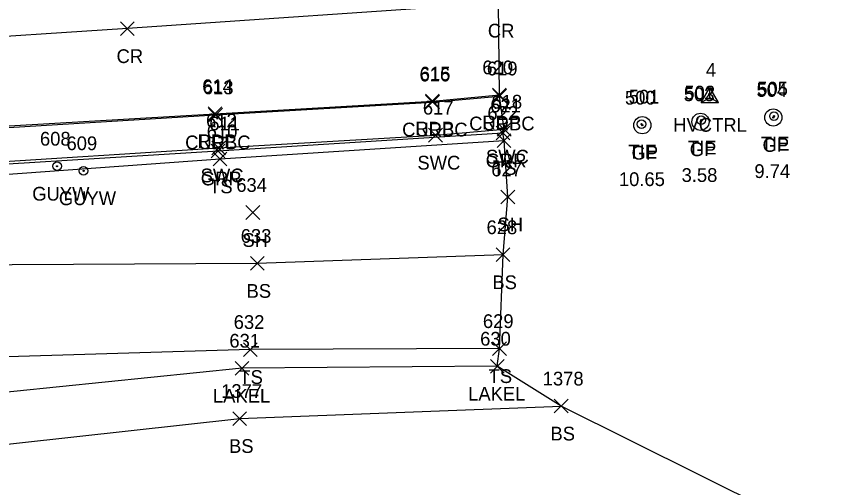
# Model space of a CAD drawing. Extents: x 1715662 to 1717487, y 887396 to 890004.
# Drawn here: x 1717358.8 to 1717478.7, y 888192.4 to 888260.9 of the extents above; entities that cross this region are included whole.
import ezdxf

# ---------------------------------------------------------------- set-up
doc = ezdxf.new("R2010")
doc.units = 0
for name, color, linetype in [('C_A', 7, 'Continuous'), ('C_C', 7, 'Continuous'), ('C_I', 7, 'Continuous'), ('CBP', 7, 'Continuous'), ('CPSM', 7, 'Continuous'), ('L_A', 7, 'Continuous'), ('L_I', 7, 'Continuous'), ('L_TIC', 7, 'Continuous'), ('LAWE', 7, 'Continuous'), ('LELB', 7, 'Continuous'), ('LSOGP', 7, 'Continuous'), ('P_A', 7, 'Continuous'), ('P_I', 7, 'Continuous'), ('P_TIC', 7, 'Continuous'), ('PET', 7, 'Continuous'), ('PRC', 7, 'Continuous'), ('R_A', 7, 'Continuous'), ('R_I', 7, 'Continuous'), ('R_TIC', 7, 'Continuous'), ('RC', 7, 'Continuous'), ('RGP', 7, 'Continuous'), ('RGR', 7, 'Continuous'), ('RSW', 7, 'Continuous'), ('U_A', 7, 'Continuous'), ('U_I', 7, 'Continuous'), ('UPGW', 7, 'Continuous')]:
    doc.layers.add(name, color=color, linetype=linetype)

msp = doc.modelspace()

# ---------------------------------------------------------------- linework, layer by layer
at = {"layer": 'CBP'}
for centre, radius in [((1717468.98, 888246.44), 0.625), ((1717449.72, 888245.27), 0.625), ((1717458.39, 888245.87), 0.625), ((1717458.39, 888245.87), 0.0833), ((1717468.98, 888246.44), 0.0833), ((1717449.72, 888245.27), 0.0833)]:
    msp.add_circle(centre, radius, dxfattribs=at)
at = {"layer": 'CPSM'}
for p, q in [((1717458.39, 888248.45), (1717459.64, 888250.62)), ((1717458.39, 888248.45), (1717459.64, 888250.62)), ((1717458.39, 888248.45), (1717459.64, 888250.62)), ((1717458.39, 888248.45), (1717459.64, 888250.62)), ((1717458.39, 888248.45), (1717459.64, 888250.62)), ((1717458.39, 888248.45), (1717459.64, 888250.62)), ((1717458.39, 888248.45), (1717459.64, 888250.62)), ((1717458.39, 888248.45), (1717459.64, 888250.62)), ((1717458.39, 888248.45), (1717459.64, 888250.62)), ((1717458.39, 888248.45), (1717459.64, 888250.61)), ((1717460.89, 888248.45), (1717459.64, 888250.62)), ((1717459.64, 888249.17), (1717459.64, 888250.62)), ((1717460.89, 888248.45), (1717459.64, 888250.62)), ((1717459.64, 888249.17), (1717459.64, 888250.62)), ((1717460.89, 888248.45), (1717459.64, 888250.62)), ((1717459.64, 888249.17), (1717459.64, 888250.62)), ((1717460.89, 888248.45), (1717459.64, 888250.62)), ((1717459.64, 888249.17), (1717459.64, 888250.62)), ((1717460.89, 888248.45), (1717459.64, 888250.62)), ((1717459.64, 888249.17), (1717459.64, 888250.62)), ((1717460.89, 888248.45), (1717459.64, 888250.62)), ((1717459.64, 888249.17), (1717459.64, 888250.62)), ((1717460.89, 888248.45), (1717459.64, 888250.62)), ((1717459.64, 888249.17), (1717459.64, 888250.62)), ((1717460.89, 888248.45), (1717459.64, 888250.62)), ((1717459.64, 888249.17), (1717459.64, 888250.62)), ((1717460.89, 888248.45), (1717459.64, 888250.62)), ((1717459.64, 888249.17), (1717459.64, 888250.62)), ((1717460.89, 888248.45), (1717459.64, 888250.61)), ((1717459.64, 888249.17), (1717459.64, 888250.61)), ((1717458.39, 888248.45), (1717459.64, 888249.17)), ((1717458.39, 888248.45), (1717459.64, 888249.17)), ((1717458.39, 888248.45), (1717459.64, 888249.17)), ((1717458.39, 888248.45), (1717459.64, 888249.17)), ((1717458.39, 888248.45), (1717459.64, 888249.17)), ((1717458.39, 888248.45), (1717459.64, 888249.17)), ((1717458.39, 888248.45), (1717459.64, 888249.17)), ((1717458.39, 888248.45), (1717459.64, 888249.17)), ((1717458.39, 888248.45), (1717459.64, 888249.17)), ((1717458.39, 888248.45), (1717459.64, 888249.17)), ((1717458.39, 888248.45), (1717460.89, 888248.45)), ((1717458.39, 888248.45), (1717460.89, 888248.45)), ((1717458.39, 888248.45), (1717460.89, 888248.45)), ((1717458.39, 888248.45), (1717460.89, 888248.45)), ((1717458.39, 888248.45), (1717460.89, 888248.45)), ((1717458.39, 888248.45), (1717460.89, 888248.45)), ((1717458.39, 888248.45), (1717460.89, 888248.45)), ((1717458.39, 888248.45), (1717460.89, 888248.45)), ((1717458.39, 888248.45), (1717460.89, 888248.45)), ((1717458.39, 888248.45), (1717460.89, 888248.45)), ((1717459.64, 888249.17), (1717459.64, 888249.17)), ((1717459.64, 888249.17), (1717460.89, 888248.45)), ((1717459.64, 888249.17), (1717459.64, 888249.17)), ((1717459.64, 888249.17), (1717460.89, 888248.45)), ((1717459.64, 888249.17), (1717459.64, 888249.17)), ((1717459.64, 888249.17), (1717460.89, 888248.45)), ((1717459.64, 888249.17), (1717459.64, 888249.17)), ((1717459.64, 888249.17), (1717460.89, 888248.45)), ((1717459.64, 888249.17), (1717459.64, 888249.17)), ((1717459.64, 888249.17), (1717460.89, 888248.45)), ((1717459.64, 888249.17), (1717459.64, 888249.17)), ((1717459.64, 888249.17), (1717460.89, 888248.45)), ((1717459.64, 888249.17), (1717459.64, 888249.17)), ((1717459.64, 888249.17), (1717460.89, 888248.45)), ((1717459.64, 888249.17), (1717459.64, 888249.17)), ((1717459.64, 888249.17), (1717460.89, 888248.45)), ((1717459.64, 888249.17), (1717459.64, 888249.17)), ((1717459.64, 888249.17), (1717460.89, 888248.45)), ((1717459.64, 888249.17), (1717459.64, 888249.17)), ((1717459.64, 888249.17), (1717460.89, 888248.45))]:
    msp.add_line(p, q, dxfattribs=at)
at = {"layer": 'L_TIC'}
for points in [[(1717428.71, 888241.89), (1717430.71, 888243.89)], [(1717430.71, 888241.89), (1717428.71, 888243.89)], [(1717387.41, 888239.22), (1717389.41, 888241.22)], [(1717389.41, 888239.22), (1717387.41, 888241.22)], [(1717429.27, 888233.68), (1717431.27, 888235.68)], [(1717431.27, 888233.68), (1717429.27, 888235.68)], [(1717392.18, 888231.42), (1717394.18, 888233.42)], [(1717394.18, 888231.42), (1717392.18, 888233.42)], [(1717428.58, 888225.27), (1717430.58, 888227.27)], [(1717430.58, 888225.27), (1717428.58, 888227.27)], [(1717392.83, 888224.01), (1717394.83, 888226.01)], [(1717394.83, 888224.01), (1717392.83, 888226.01)], [(1717391.81, 888211.48), (1717393.81, 888213.48)], [(1717393.81, 888211.48), (1717391.81, 888213.48)], [(1717428.06, 888211.61), (1717430.06, 888213.61)], [(1717430.06, 888211.61), (1717428.06, 888213.61)], [(1717427.73, 888209.05), (1717429.73, 888211.05)], [(1717429.73, 888209.05), (1717427.73, 888211.05)], [(1717390.62, 888208.76), (1717392.62, 888210.76)], [(1717392.62, 888208.76), (1717390.62, 888210.76)], [(1717437.03, 888203.25), (1717439.03, 888205.25)], [(1717439.03, 888203.25), (1717437.03, 888205.25)], [(1717390.28, 888201.44), (1717392.28, 888203.44)], [(1717392.28, 888201.44), (1717390.28, 888203.44)]]:
    msp.add_lwpolyline(points, dxfattribs=at)
at = {"layer": 'LAWE'}
msp.add_lwpolyline([(1717428.73, 888210.05), (1717391.62, 888209.76), (1717351.71, 888205.71), (1717299.91, 888205.55), (1717265.68, 888204.48), (1717223.67, 888200.84), (1717208.56, 888201.76), (1717201.77, 888208.17), (1717191.38, 888215.04), (1717175.77, 888226.39)], dxfattribs=at)
at = {"layer": 'LELB'}
for points in [[(1717168.22, 888251.6), (1717169.76, 888223.63), (1717177.45, 888214.69), (1717194.47, 888204.09), (1717205.17, 888197.96), (1717222.8, 888195.9), (1717272.16, 888195.5), (1717301.8, 888198.15), (1717342.96, 888197.13), (1717391.28, 888202.44), (1717438.03, 888204.25)], [(1717195, 888228.65), (1717213.42, 888229.75), (1717254.51, 888232.62), (1717289.45, 888234.25), (1717344.86, 888237.07), (1717388.41, 888240.22), (1717429.71, 888242.89)], [(1717429.58, 888226.27), (1717393.83, 888225.01), (1717349.19, 888224.75), (1717340.99, 888224.94), (1717302.22, 888221.68), (1717265.44, 888218.58), (1717217.95, 888213.61)], [(1717429.06, 888212.61), (1717392.81, 888212.48), (1717352.66, 888211.27), (1717300.92, 888208.21), (1717265.27, 888207.12), (1717222.12, 888203.99)]]:
    msp.add_lwpolyline(points, dxfattribs=at)
at = {"layer": 'LSOGP'}
msp.add_lwpolyline([(1717478.65, 888184.02), (1717438.03, 888204.25), (1717428.73, 888210.05), (1717429.05, 888212.6), (1717429.57, 888226.27), (1717430.27, 888234.68), (1717429.72, 888242.9), (1717429.56, 888243.99), (1717429.73, 888244.54), (1717429.07, 888249.37), (1717429.05, 888249.53), (1717428.93, 888262.88), (1717427.28, 888275.56), (1717425.76, 888281.26), (1717425.72, 888293.07), (1717424.15, 888313.25), (1717427.07, 888329.96), (1717411.38, 888343.28), (1717406.07, 888347.48), (1717401.94, 888364.63), (1717397.44, 888368.91), (1717347.56, 888372.82)], dxfattribs=at)
at = {"layer": 'P_TIC'}
for points in [[(1717373.93, 888258.17), (1717375.93, 888260.17)], [(1717375.93, 888258.17), (1717373.93, 888260.17)], [(1717428.05, 888248.53), (1717430.05, 888250.53)], [(1717430.05, 888248.53), (1717428.05, 888250.53)], [(1717418.3, 888247.63), (1717420.3, 888249.63)], [(1717420.3, 888247.63), (1717418.3, 888249.63)], [(1717386.67, 888245.79), (1717388.67, 888247.79)], [(1717388.67, 888245.79), (1717386.67, 888247.79)]]:
    msp.add_lwpolyline(points, dxfattribs=at)
at = {"layer": 'PET'}
msp.add_lwpolyline([(1717427.27, 888275.57), (1717374.24, 888271.92), (1717317.86, 888268.58), (1717270, 888265.54), (1717231.18, 888263.33), (1717177.06, 888260.69), (1717177.8, 888248.05), (1717178.6, 888236.51), (1717214.03, 888237.98), (1717254.52, 888239.74), (1717289.28, 888241.31), (1717339.42, 888243.96), (1717387.67, 888246.79), (1717419.3, 888248.63), (1717429.05, 888249.53)], dxfattribs=at)
at = {"layer": 'PRC'}
msp.add_lwpolyline([(1717428.93, 888262.88), (1717374.93, 888259.17), (1717318.78, 888255.52), (1717271.43, 888252.69), (1717231.27, 888251.09), (1717177.8, 888248.05)], dxfattribs=at)
at = {"layer": 'R_TIC'}
for points in [[(1717418.31, 888247.49), (1717420.31, 888249.49)], [(1717420.31, 888247.49), (1717418.31, 888249.49)], [(1717428.07, 888248.37), (1717430.07, 888250.37)], [(1717430.07, 888248.37), (1717428.07, 888250.37)], [(1717386.75, 888245.62), (1717388.75, 888247.62)], [(1717388.75, 888245.62), (1717386.75, 888247.62)], [(1717418.75, 888242.67), (1717420.75, 888244.67)], [(1717420.75, 888242.67), (1717418.75, 888244.67)], [(1717428.56, 888242.99), (1717430.56, 888244.99)], [(1717430.56, 888242.99), (1717428.56, 888244.99)], [(1717428.73, 888243.54), (1717430.73, 888245.54)], [(1717430.73, 888243.54), (1717428.73, 888245.54)], [(1717387.12, 888240.37), (1717389.12, 888242.37)], [(1717389.12, 888240.37), (1717387.12, 888242.37)], [(1717387.22, 888240.81), (1717389.22, 888242.81)], [(1717389.22, 888240.81), (1717387.22, 888242.81)]]:
    msp.add_lwpolyline(points, dxfattribs=at)
at = {"layer": 'RC'}
msp.add_lwpolyline([(1717178.77, 888236.27), (1717214.14, 888237.8), (1717254.52, 888239.57), (1717289.15, 888241.08), (1717339.38, 888243.69), (1717387.75, 888246.62), (1717419.31, 888248.49), (1717429.07, 888249.37)], dxfattribs=at)
at = {"layer": 'RGP'}
for p, q in [((1717468.88, 888246.25), (1717468.88, 888246.25)), ((1717449.83, 888245.12), (1717449.83, 888245.12)), ((1717458.29, 888245.62), (1717458.29, 888245.62))]:
    msp.add_line(p, q, dxfattribs=at)
for centre, radius in [((1717468.88, 888246.25), 1.25), ((1717449.83, 888245.12), 1.25), ((1717458.29, 888245.62), 1.25), ((1717458.29, 888245.62), 0.0833), ((1717468.88, 888246.25), 0.0833), ((1717449.83, 888245.12), 0.0833)]:
    msp.add_circle(centre, radius, dxfattribs=at)
at = {"layer": 'RGR'}
msp.add_lwpolyline([(1717180.01, 888230.78), (1717185.31, 888230.2), (1717193.48, 888230.86), (1717213.85, 888231.84), (1717254.51, 888233.87), (1717289.66, 888235.62), (1717339.45, 888238.4), (1717388.12, 888241.37), (1717429.56, 888243.99)], dxfattribs=at)
at = {"layer": 'RSW'}
msp.add_lwpolyline([(1717178.7, 888235.76), (1717178.9, 888231.46), (1717213.38, 888232.72), (1717254.44, 888234.73), (1717289.86, 888236.28), (1717339.5, 888238.74), (1717388.22, 888241.81), (1717419.75, 888243.67), (1717429.73, 888244.54)], dxfattribs=at)
at = {"layer": 'UPGW'}
for centre, radius in [((1717364.71, 888239.15), 0.625), ((1717364.71, 888239.15), 0.0833), ((1717368.57, 888238.49), 0.625), ((1717368.57, 888238.49), 0.0833)]:
    msp.add_circle(centre, radius, dxfattribs=at)

# ---------------------------------------------------------------- texts
at = {"layer": 'C_A'}
for s, p in [('HVCTRL', (1717454.33, 888244.17)), ('HVCTRL', (1717454.33, 888244.17)), ('HVCTRL', (1717454.33, 888244.17)), ('HVCTRL', (1717454.33, 888244.17)), ('HVCTRL', (1717454.33, 888244.17)), ('HVCTRL', (1717454.33, 888244.17)), ('HVCTRL', (1717454.33, 888244.17)), ('HVCTRL', (1717454.33, 888244.17)), ('HVCTRL', (1717454.33, 888244.17)), ('HVCTRL', (1717454.33, 888244.17)), ('TIE', (1717467.06, 888241.44)), ('TIE', (1717447.8, 888240.27)), ('TIE', (1717456.47, 888240.87))]:
    msp.add_text(s, height=2, dxfattribs=at).set_placement(p)
at = {"layer": 'C_C'}
for s, p in [('3.58', (1717455.54, 888236.87)), ('9.74', (1717466.13, 888237.44)), ('10.65', (1717446.42, 888236.27))]:
    msp.add_text(s, height=2, dxfattribs=at).set_placement(p)
at = {"layer": 'C_I'}
for s, p in [('4', (1717459.07, 888252.17)), ('4', (1717459.07, 888252.17)), ('4', (1717459.07, 888252.17)), ('4', (1717459.07, 888252.17)), ('4', (1717459.07, 888252.17)), ('4', (1717459.07, 888252.17)), ('4', (1717459.07, 888252.17)), ('4', (1717459.07, 888252.17)), ('4', (1717459.07, 888252.17)), ('4', (1717459.07, 888252.17)), ('502', (1717455.95, 888248.87)), ('505', (1717466.54, 888249.44)), ('501', (1717447.85, 888248.27))]:
    msp.add_text(s, height=2, dxfattribs=at).set_placement(p)
at = {"layer": 'L_A'}
for s, p in [('TS', (1717428.12, 888237.89)), ('TS', (1717386.82, 888235.22)), ('SH', (1717428.76, 888229.68)), ('SH', (1717391.67, 888227.42)), ('BS', (1717428.02, 888221.27)), ('BS', (1717392.27, 888220.01)), ('TS', (1717391.22, 888207.48)), ('TS', (1717427.47, 888207.61)), ('LAKEL', (1717387.38, 888204.76)), ('LAKEL', (1717424.5, 888205.05)), ('BS', (1717436.47, 888199.25)), ('BS', (1717389.72, 888197.44))]:
    msp.add_text(s, height=2, dxfattribs=at).set_placement(p)
at = {"layer": 'L_I'}
for s, p in [('622', (1717427.3, 888245.89)), ('610', (1717386.48, 888243.22)), ('627', (1717427.86, 888237.68)), ('634', (1717390.77, 888235.42)), ('628', (1717427.17, 888229.27)), ('633', (1717391.42, 888228.01)), ('632', (1717390.4, 888215.48)), ('629', (1717426.64, 888215.61)), ('631', (1717389.77, 888212.76)), ('630', (1717426.24, 888213.05)), ('1378', (1717435.34, 888207.25)), ('1377', (1717388.58, 888205.44))]:
    msp.add_text(s, height=2, dxfattribs=at).set_placement(p)
at = {"layer": 'P_A'}
for s, p in [('CR', (1717427.36, 888257.88)), ('CR', (1717373.36, 888254.17)), ('RDP', (1717426.54, 888244.53)), ('RDP', (1717416.79, 888243.63)), ('RDP', (1717385.15, 888241.79))]:
    msp.add_text(s, height=2, dxfattribs=at).set_placement(p)
at = {"layer": 'P_I'}
for s, p in [('620', (1717426.56, 888252.53)), ('615', (1717417.46, 888251.63)), ('614', (1717385.82, 888249.79))]:
    msp.add_text(s, height=2, dxfattribs=at).set_placement(p)
at = {"layer": 'R_A'}
for s, p in [('CURBC', (1717424.65, 888244.37)), ('CURBC', (1717414.9, 888243.49)), ('CURBC', (1717383.34, 888241.62)), ('GP', (1717448.26, 888240.12)), ('GP', (1717456.72, 888240.62)), ('GP', (1717467.31, 888241.25)), ('GRR', (1717427.04, 888238.99)), ('SWC', (1717427.09, 888239.54)), ('SWC', (1717417.12, 888238.67)), ('SWC', (1717385.59, 888236.81)), ('GRR', (1717385.61, 888236.37))]:
    msp.add_text(s, height=2, dxfattribs=at).set_placement(p)
at = {"layer": 'R_I'}
for s, p in [('619', (1717427.22, 888252.37)), ('616', (1717417.42, 888251.49)), ('613', (1717385.91, 888249.62)), ('503', (1717455.85, 888248.62)), ('504', (1717466.43, 888249.25)), ('618', (1717427.89, 888247.54)), ('500', (1717447.3, 888248.12)), ('617', (1717417.91, 888246.67)), ('621', (1717427.71, 888246.99)), ('612', (1717386.38, 888244.81)), ('611', (1717386.84, 888244.37))]:
    msp.add_text(s, height=2, dxfattribs=at).set_placement(p)
at = {"layer": 'U_A'}
for p in [(1717361.1, 888234.15), (1717364.97, 888233.49)]:
    msp.add_text('GUYW', height=2, dxfattribs=at).set_placement(p)
at = {"layer": 'U_I'}
for s, p in [('608', (1717362.22, 888242.15)), ('609', (1717366.08, 888241.49))]:
    msp.add_text(s, height=2, dxfattribs=at).set_placement(p)

doc.saveas('drawing.dxf')
